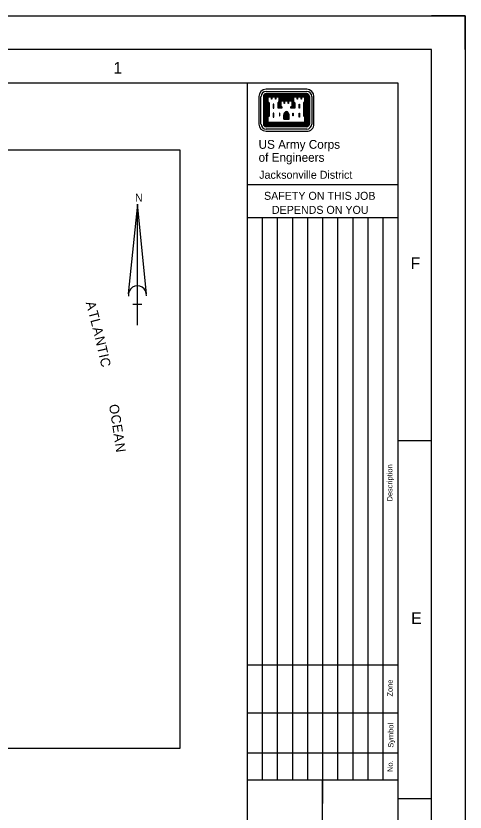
# Model space of a CAD drawing. Extents: x 315926 to 491925, y 1158891 to 1294891.
# Drawn here: x 465125 to 491925, y 1247430 to 1294891 of the extents above; entities that cross this region are included whole.
import ezdxf

# ---------------------------------------------------------------- set-up
doc = ezdxf.new("R2010")
doc.units = 0
for name, color, linetype in [('G-ANNO-NPLT', 7, 'Continuous'), ('G-ANNO-TEXT-LOGO', 7, 'Continuous'), ('G-ANNO-TEXT-TTLB', 7, 'Continuous'), ('G-ANNO-TTLB', 7, 'Continuous'), ('V-ANNO-SYMB', 7, 'Continuous')]:
    doc.layers.add(name, color=color, linetype=linetype)

msp = doc.modelspace()

# ---------------------------------------------------------------- linework, layer by layer
at = {"layer": 'G-ANNO-NPLT'}
msp.add_lwpolyline([(315926, 1294891), (491925, 1294891), (491925, 1158891), (315926, 1158891)], close=True, dxfattribs=at)
msp.add_lwpolyline([(491925, 1292891), (491925, 1294891), (489925, 1294891)], dxfattribs=at)
at = {"layer": 'G-ANNO-TEXT-LOGO'}
for p, q in [((482480, 1290515), (480048, 1290515)), ((479620, 1290087), (479620, 1288447)), ((479748, 1288447), (479748, 1290087)), ((479888, 1290087), (479888, 1288447)), ((479924, 1290087), (479924, 1288447)), ((479956, 1290087), (479956, 1288447)), ((479992, 1290087), (479992, 1288447)), ((480028, 1290087), (480028, 1288447)), ((480048, 1290387), (482480, 1290387)), ((482480, 1290251), (480048, 1290251)), ((482480, 1290215), (480048, 1290215)), ((482480, 1290179), (480048, 1290179)), ((482480, 1290147), (480048, 1290147)), ((482480, 1290111), (480048, 1290111)), ((480064, 1290087), (480064, 1288459)), ((480096, 1290087), (480096, 1288495)), ((480892, 1290079), (481636, 1290079)), ((480892, 1290043), (481636, 1290043)), ((480892, 1290011), (481636, 1290011)), ((480892, 1289975), (481636, 1289975)), ((482432, 1290087), (482432, 1288495)), ((482464, 1290087), (482464, 1288459)), ((482500, 1290087), (482500, 1288447)), ((482536, 1290087), (482536, 1288447)), ((482568, 1290087), (482568, 1288447)), ((482604, 1290087), (482604, 1288447)), ((482640, 1290087), (482640, 1288447)), ((482776, 1290087), (482776, 1288447)), ((482908, 1288447), (482908, 1290087)), ((480124, 1289739), (480124, 1288899)), ((480160, 1289703), (480160, 1288939)), ((480892, 1289939), (481636, 1289939)), ((480892, 1289907), (481636, 1289907)), ((480892, 1289871), (481636, 1289871)), ((482368, 1289703), (482368, 1288939)), ((482404, 1289735), (482404, 1288903)), ((481104, 1288731), (481104, 1288999)), ((481104, 1288731), (481424, 1288731)), ((481136, 1288731), (481136, 1288999)), ((481172, 1288731), (481172, 1288999)), ((481208, 1288731), (481208, 1288999)), ((481240, 1288731), (481240, 1288999)), ((481288, 1288731), (481288, 1288999)), ((481320, 1288731), (481320, 1288999)), ((481356, 1288731), (481356, 1288999)), ((481392, 1288731), (481392, 1288999)), ((481424, 1288731), (481424, 1288999)), ((482480, 1288423), (480048, 1288423)), ((482480, 1288391), (480048, 1288391)), ((482480, 1288355), (480048, 1288355)), ((482480, 1288319), (480048, 1288319)), ((482480, 1288287), (480048, 1288287)), ((482480, 1288147), (480048, 1288147)), ((482464, 1288459), (480064, 1288459)), ((482432, 1288495), (480096, 1288495)), ((480048, 1288015), (482480, 1288015))]:
    msp.add_line(p, q, dxfattribs=at)
for points in [[(480124, 1290087), (480124, 1289771), (480192, 1289703), (480192, 1288939), (480124, 1288867), (480124, 1288519), (482404, 1288519), (482404, 1288867), (482332, 1288939), (482332, 1289703), (482404, 1289771), (482404, 1290087), (482104, 1290087), (481872, 1290087), (481656, 1290087), (481656, 1289771), (481732, 1289703), (481732, 1289423), (481564, 1289423), (481564, 1289451), (481636, 1289523), (481636, 1289835), (481336, 1289835), (481104, 1289835), (480892, 1289835), (480892, 1289523), (480964, 1289451), (480964, 1289423), (480796, 1289423), (480796, 1289703), (480868, 1289771), (480868, 1290087), (480568, 1290087), (480336, 1290087), (480124, 1290087)], [(480156, 1290051), (480156, 1289787), (480228, 1289715), (480228, 1288923), (480156, 1288851), (480156, 1288555), (482372, 1288555), (482372, 1288851), (482296, 1288923), (482296, 1289715), (482372, 1289787), (482372, 1290051), (482156, 1290051), (482156, 1289927), (482136, 1289927), (482136, 1290051), (481924, 1290051), (481924, 1289927), (481908, 1289927), (481908, 1290051), (481692, 1290051), (481692, 1289787), (481764, 1289715), (481764, 1289391), (481532, 1289391), (481532, 1289467), (481604, 1289539), (481604, 1289803), (481388, 1289803), (481388, 1289679), (481372, 1289679), (481372, 1289803), (481156, 1289803), (481156, 1289679), (481136, 1289679), (481136, 1289803), (480924, 1289803), (480924, 1289539), (480996, 1289467), (480996, 1289391), (480764, 1289391), (480764, 1289715), (480836, 1289787), (480836, 1290051), (480624, 1290051), (480624, 1289927), (480604, 1289927), (480604, 1290051), (480388, 1290051), (480388, 1289927), (480372, 1289927), (480372, 1290051), (480156, 1290051)], [(480484, 1289623), (480484, 1289391), (480508, 1289391), (480508, 1289623), (480484, 1289623)], [(480852, 1289707), (480832, 1289687), (480832, 1289459), (480908, 1289459), (480856, 1289511), (480856, 1289711)], [(481676, 1289707), (481696, 1289687), (481696, 1289459), (481624, 1289459), (481672, 1289511), (481672, 1289711)], [(482040, 1289623), (482040, 1289391), (482020, 1289391), (482020, 1289623), (482040, 1289623)], [(480484, 1289091), (480484, 1288855), (480508, 1288855), (480508, 1289091), (480484, 1289091)], [(480852, 1289091), (480852, 1288927), (480872, 1288927), (480872, 1289091), (480852, 1289091)], [(481676, 1289091), (481676, 1288927), (481656, 1288927), (481656, 1289091), (481676, 1289091)], [(482040, 1289091), (482040, 1288855), (482020, 1288855), (482020, 1289091), (482040, 1289091)]]:
    msp.add_lwpolyline(points, dxfattribs=at)
for centre, major_axis, start_param, end_param in [((480049, 1290088), (429, 0), 1.57078, 3.141576), ((482477, 1290088), (429, 0), 6.283169, 7.853965), ((480049, 1290088), (300, 0), 1.57078, 3.141576), ((480049, 1290088), (161, 0), 1.57078, 3.141576), ((480049, 1290088), (126, 0), 1.57078, 3.141576), ((480049, 1290088), (91.3, 0), 1.57078, 3.141576), ((480049, 1290088), (56.5, 0), 1.57078, 3.141576), ((480049, 1290088), (21.8, 0), 1.57078, 3.141576), ((482477, 1290088), (300, 0), 6.28317, 7.853966), ((482477, 1290088), (161, 0), 6.283169, 7.853965), ((482477, 1290088), (126, 0), 6.283169, 7.853965), ((482477, 1290088), (91.3, 0), 6.283169, 7.853965), ((482477, 1290088), (56.5, 0), 6.283169, 7.853965), ((482477, 1290088), (21.8, 0), 6.283169, 7.853965), ((481323, 1288981), (-222, 0), 4.985832, 6.214359), ((481323, 1288981), (-187, 0), 4.947465, 6.21436), ((481323, 1288981), (-153, 0), 4.947465, 6.21436), ((481323, 1288981), (-118, 0), 4.947465, 6.21436), ((481203, 1288981), (83.3, 0), 0.068794, 1.335689), ((481203, 1288981), (118, 0), 0.068794, 1.335689), ((481203, 1288981), (153, 0), 0.068795, 1.335689), ((481323, 1288981), (-83.3, 0), 4.947465, 6.214359), ((481203, 1288981), (187, 0), 0.068795, 1.335689), ((481203, 1288981), (222, 0), 0.068795, 1.29842), ((480049, 1288446), (-429, 0), 6.28317, 7.853966), ((480049, 1288446), (-300, 0), 6.28317, 7.853966), ((480049, 1288446), (-161, 0), 6.28317, 7.853966), ((480049, 1288446), (-126, 0), 6.28317, 7.853966), ((480049, 1288446), (-91.3, 0), 6.28317, 7.853966), ((480049, 1288446), (-56.5, 0), 6.28317, 7.853966), ((480049, 1288446), (-21.8, 0), 6.28317, 7.853966), ((482477, 1288446), (161, 0), 4.712373, 6.28317), ((482477, 1288446), (126, 0), 4.712373, 6.28317), ((482477, 1288446), (91.3, 0), 4.712373, 6.28317), ((482477, 1288446), (56.5, 0), 4.712373, 6.28317), ((482477, 1288446), (21.8, 0), 4.712373, 6.28317), ((482477, 1288446), (429, 0), 4.712373, 6.28317), ((482477, 1288446), (-300, 0), 1.570781, 3.141577)]:
    msp.add_ellipse(centre, major_axis=major_axis, ratio=0.99964, start_param=start_param, end_param=end_param, dxfattribs=at)
at = {"layer": 'G-ANNO-TTLB'}
for p, q in [((478924, 1290891), (478924, 1162891)), ((478925, 1284841), (487925, 1284841)), ((478901, 1282876), (487901, 1282876)), ((479818, 1282876), (479818, 1249360)), ((480718, 1282876), (480718, 1249360)), ((481618, 1282876), (481618, 1249360)), ((482518, 1282876), (482518, 1249360)), ((483418, 1282876), (483418, 1249360)), ((484318, 1282876), (484318, 1249360)), ((485218, 1282876), (485218, 1249360)), ((486118, 1282876), (486118, 1249360)), ((487018, 1282876), (487018, 1249360)), ((489925, 1269551), (487925, 1269551)), ((478925, 1256201), (487925, 1256201)), ((478925, 1253354), (487925, 1253354)), ((478925, 1250954), (487925, 1250952)), ((478925, 1249360), (487925, 1249360)), ((483399, 1214977), (483425, 1249360)), ((483425, 1249360), (483424, 1247944)), ((489925, 1248219), (487925, 1248219))]:
    msp.add_line(p, q, dxfattribs=at)
for points in [[(317926, 1160891), (489925, 1160891), (489925, 1292891), (317926, 1292891)], [(487925, 1290891), (322926, 1290891), (322926, 1162891), (487925, 1162891)]]:
    msp.add_lwpolyline(points, close=True, dxfattribs=at)
at = {"layer": 'V-ANNO-SYMB'}
for p, q in [((474924, 1286891), (435411, 1286891)), ((474924, 1251239), (474924, 1286891)), ((471834, 1278321), (472390, 1283663)), ((472371, 1276465), (472371, 1283665)), ((472909, 1278318), (472387, 1283667)), ((472099, 1277707), (472639, 1277707)), ((435411, 1251239), (474924, 1251239))]:
    msp.add_line(p, q, dxfattribs=at)
msp.add_arc((472371, 1278265), 540, 353.3459, 188.7908, dxfattribs=at)

# ---------------------------------------------------------------- texts
at = {"layer": 'G-ANNO-TEXT-TTLB'}
for s, height, p in [('US Army Corps', 523.44, (479604, 1286971)), ('of Engineers', 523.44, (479604, 1286195)), ('Jacksonville District', 475.99, (479644, 1285183)), ('SAFETY ON THIS JOB', 476, (479929, 1283928)), ('DEPENDS ON YOU', 476, (480400, 1283092))]:
    msp.add_text(s, height=height, dxfattribs=at).set_placement(p)
for s, p in [('Description', (487590, 1265949)), ('Zone', (487602, 1254321)), ('Symbol', (487649, 1251268)), ('No.', (487609, 1249823))]:
    msp.add_text(s, height=320, rotation=90, dxfattribs=at).set_placement(p)
at = {"layer": 'G-ANNO-TTLB'}
for s, p in [('1', (470942, 1291444)), ('F', (488677, 1279798)), ('E', (488708, 1258644))]:
    msp.add_text(s, height=700, dxfattribs=at).set_placement(p)
at = {"layer": 'V-ANNO-SYMB'}
for s, height, rotation, p in [('N', 472, 0, (472234, 1283824)), ('A', 576, 285.3188, (469285, 1277794)), ('T', 576, 284.8034, (469438, 1277233)), ('L', 576, 284.3674, (469564, 1276758)), ('A', 576, 283.9315, (469687, 1276281)), ('N', 576, 283.4161, (469827, 1275717)), ('T', 576, 282.9008, (469961, 1275152)), ('I', 576, 282.4648, (470072, 1274673)), ('C', 576, 282.2667, (470120, 1274455)), ('O', 576, 279.7701, (470671, 1271693)), ('C', 576, 279.215, (470777, 1271076)), ('E', 576, 278.6996, (470870, 1270502)), ('A', 576, 278.2236, (470951, 1269972)), ('N', 576, 277.7082, (471035, 1269396))]:
    msp.add_text(s, height=height, rotation=rotation, dxfattribs=at).set_placement(p)

doc.saveas('drawing.dxf')
